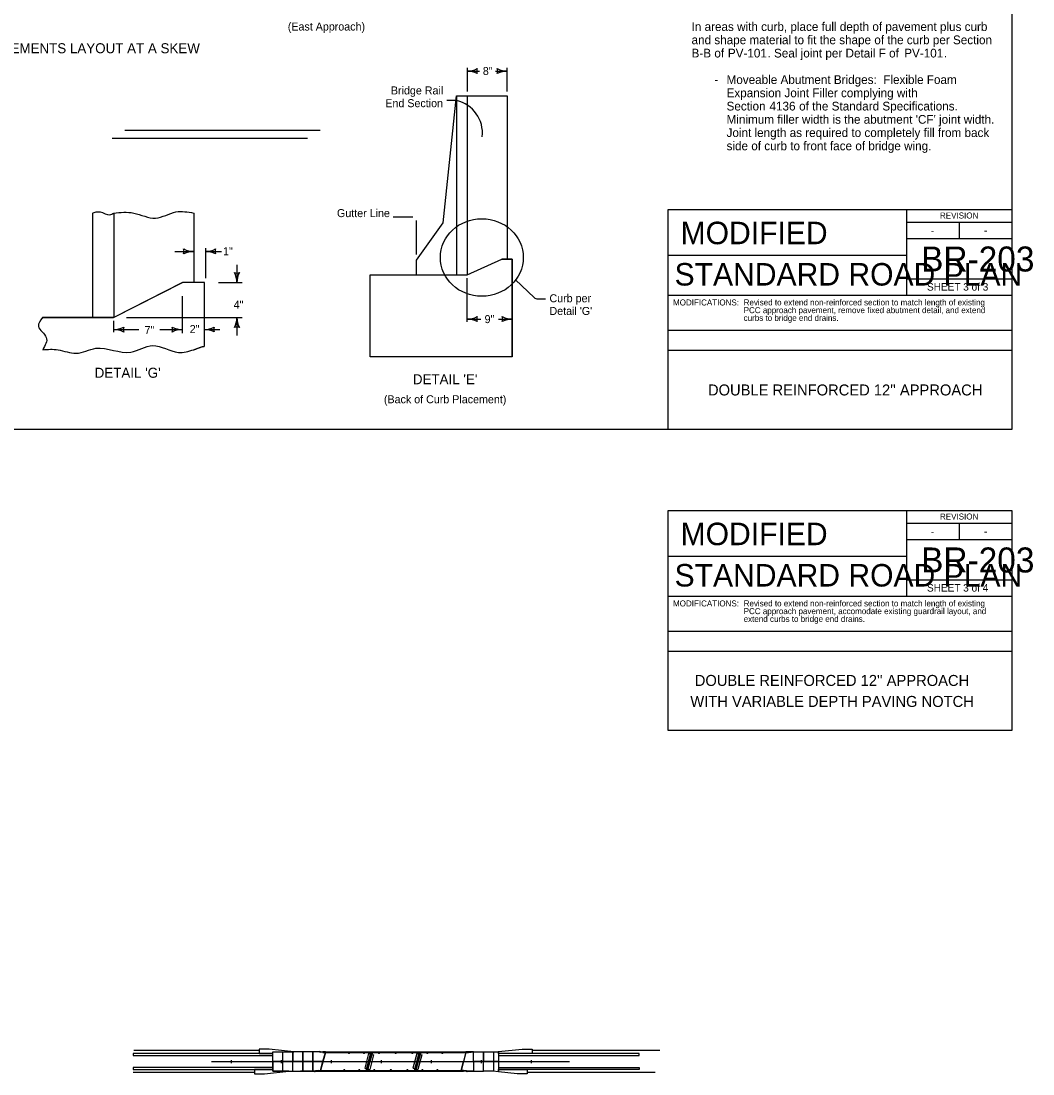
# Model space of a CAD drawing. Extents: x 5546 to 81668, y 3174 to 15999.
# Drawn here: x 18485 to 20510, y 6635 to 8741 of the extents above; entities that cross this region are included whole.
import ezdxf

# ---------------------------------------------------------------- set-up
doc = ezdxf.new("R2010")
doc.units = 0
for name, color, linetype in [('Annotation', 7, 'Continuous'), ('Level 61', 7, 'Continuous'), ('PS_BOLT', 7, 'Continuous'), ('PS_CONST', 7, 'Continuous'), ('PS_DIM', 7, 'Continuous'), ('SheetAddenda', 7, 'Continuous'), ('ShtPlotIdentification', 7, 'Continuous'), ('Table Border', 7, 'Continuous'), ('tdCoLegendColorEntry', 7, 'Continuous'), ('tdCoLegendTitle', 7, 'Continuous'), ('tdCoShieldCoRte', 7, 'Continuous'), ('tdCoShieldUsRte', 7, 'Continuous')]:
    doc.layers.add(name, color=color, linetype=linetype)

msp = doc.modelspace()

# ---------------------------------------------------------------- linework, layer by layer
at = {"layer": 'Annotation'}
for p, q in [((19082.1, 6679.9), (19082.2, 6680)), ((19082.1, 6679.9), (19083.8, 6679.9)), ((19082.1, 6679.9), (19083.8, 6678.9)), ((19082.5, 6680.6), (19082.2, 6680)), ((19082.2, 6680), (19083.9, 6679)), ((19084.1, 6679.7), (19082.5, 6680.6)), ((19083.8, 6679.9), (19089.1, 6679.9)), ((19089.1, 6678.9), (19083.8, 6678.9)), ((19089.1, 6679), (19083.9, 6679)), ((19084.4, 6679.7), (19084.4, 6678.9)), ((19094.1, 6678.3), (19084.4, 6642.3)), ((19089.1, 6678.3), (19084.6, 6678.9)), ((19085.5, 6679.7), (19085.5, 6678.9)), ((19086.2, 6679.7), (19086.2, 6678.9)), ((19089.1, 6679.9), (19380.1, 6679.9)), ((19089.1, 6678.3), (19089.1, 6679.9)), ((19094.3, 6679.7), (19089.1, 6679.7)), ((19094.3, 6679), (19089.1, 6679)), ((19094.3, 6678.9), (19089.1, 6678.9)), ((19089.1, 6678.3), (19380.1, 6678.3)), ((19094.1, 6678.3), (19094.1, 6679.9)), ((19180.3, 6676.1), (19172.6, 6647.2)), ((19185.1, 6679.8), (19174.9, 6641.6)), ((19188.2, 6679), (19177.9, 6640.8)), ((19180.3, 6676.1), (19190.5, 6673.4)), ((19185.1, 6679.8), (19188.2, 6679)), ((19276.8, 6676.1), (19269.1, 6647.2)), ((19281.6, 6679.8), (19271.4, 6641.6)), ((19284.7, 6679), (19274.5, 6640.8)), ((19276.8, 6676.1), (19287, 6673.4)), ((19281.6, 6679.8), (19284.7, 6679)), ((19375.2, 6678.3), (19365.5, 6642.3)), ((19380.1, 6679.7), (19374.9, 6679.7)), ((19380.1, 6679), (19374.9, 6679)), ((19380.1, 6678.9), (19374.9, 6678.9)), ((19375.2, 6678.3), (19375.2, 6679.9)), ((19380.1, 6678.3), (19380.1, 6679.9)), ((19385.4, 6679.9), (19380.1, 6679.9)), ((19380.1, 6679), (19385.3, 6679)), ((19380.1, 6678.9), (19385.4, 6678.9)), ((19380.1, 6678.3), (19384.6, 6678.9)), ((19383, 6679.7), (19383, 6678.9)), ((19383.7, 6679.7), (19383.7, 6678.9)), ((19384.8, 6679.7), (19384.8, 6678.9)), ((19385.2, 6679.7), (19386.7, 6680.6)), ((19387, 6680), (19385.3, 6679)), ((19387.1, 6679.9), (19385.4, 6679.9)), ((19387.1, 6679.9), (19385.4, 6678.9)), ((19386.7, 6680.6), (19387, 6680)), ((19387.1, 6679.9), (19387, 6680)), ((19182.8, 6669.8), (19177.9, 6651.4)), ((19185.2, 6669.2), (19180.3, 6650.8)), ((19190.5, 6673.4), (19182.7, 6644.5)), ((19182.8, 6671.3), (19185.9, 6670.5)), ((19279.3, 6669.8), (19274.4, 6651.4)), ((19281.7, 6669.2), (19276.8, 6650.8)), ((19287, 6673.4), (19279.2, 6644.5)), ((19279.3, 6671.3), (19282.4, 6670.5)), ((19072.5, 6640.7), (19074.2, 6641.7)), ((19072.5, 6640.6), (19074.2, 6641.5)), ((19072.5, 6640.7), (19074.1, 6640.7)), ((19072.5, 6640.7), (19072.5, 6640.6)), ((19072.9, 6640), (19072.5, 6640.6)), ((19074.4, 6640.9), (19072.9, 6640)), ((19074.1, 6640.7), (19079.5, 6640.7)), ((19079.5, 6641.7), (19074.2, 6641.7)), ((19079.5, 6641.5), (19074.2, 6641.5)), ((19074.8, 6640.9), (19074.8, 6641.7)), ((19079.5, 6642.3), (19075, 6641.7)), ((19075.9, 6640.9), (19075.9, 6641.7)), ((19076.5, 6640.9), (19076.5, 6641.7)), ((19079.5, 6642.3), (19079.5, 6640.7)), ((19079.5, 6640.9), (19079.5, 6642.3)), ((19079.5, 6642.3), (19370.5, 6642.3)), ((19084.7, 6641.7), (19079.5, 6641.7)), ((19084.7, 6641.5), (19079.5, 6641.5)), ((19084.7, 6640.9), (19079.5, 6640.9)), ((19079.5, 6640.7), (19370.5, 6640.7)), ((19084.4, 6640.7), (19084.4, 6642.3)), ((19172.6, 6647.2), (19182.7, 6644.5)), ((19174.9, 6641.6), (19177.9, 6640.8)), ((19177.2, 6650.1), (19180.2, 6649.3)), ((19269.1, 6647.2), (19279.2, 6644.5)), ((19271.4, 6641.6), (19274.5, 6640.8)), ((19273.7, 6650.1), (19276.7, 6649.3)), ((19370.5, 6641.5), (19365.2, 6641.5)), ((19370.5, 6640.9), (19365.2, 6640.9)), ((19370.5, 6641.7), (19365.3, 6641.7)), ((19365.5, 6640.7), (19365.5, 6642.3)), ((19370.5, 6642.3), (19370.5, 6640.7)), ((19370.5, 6642.3), (19374.9, 6641.7)), ((19370.5, 6641.7), (19375.7, 6641.7)), ((19370.5, 6641.5), (19375.7, 6641.5)), ((19375.8, 6640.7), (19370.5, 6640.7)), ((19373.4, 6640.9), (19373.4, 6641.7)), ((19374.1, 6640.9), (19374.1, 6641.7)), ((19375.1, 6640.9), (19375.1, 6641.7)), ((19375.5, 6640.9), (19377, 6640)), ((19376.6, 6641.2), (19375.7, 6641.7)), ((19377.4, 6640.6), (19375.7, 6641.5)), ((19377.5, 6640.7), (19375.8, 6640.7)), ((19377, 6640), (19377.4, 6640.6)), ((19377.5, 6640.7), (19377.4, 6640.6))]:
    msp.add_line(p, q, dxfattribs=at)
for points in [[(19084.1, 6679.7), (19089.1, 6679.7), (19089.1, 6679.7), (19089.1, 6679.7)], [(19385.2, 6679.7), (19380.1, 6679.7), (19380.1, 6679.7), (19380.1, 6679.7)], [(19074.4, 6640.9), (19079.5, 6640.9), (19079.5, 6640.9), (19079.5, 6640.9)], [(19375.5, 6640.9), (19370.5, 6640.9), (19370.5, 6640.9), (19370.5, 6640.9)]]:
    msp.add_lwpolyline(points, dxfattribs=at)
for centre, radius, start, end in [((19141.4, 6678.3), 1.5, 180, 0), ((19171.4, 6678.3), 1.5, 180, 0), ((19201.4, 6678.3), 1.5, 180, 0), ((19234.6, 6678.3), 1.5, 180, 0), ((19267.9, 6678.3), 1.5, 180, 0), ((19297.9, 6678.3), 1.5, 180, 0), ((19327.9, 6678.3), 1.5, 180, 0), ((19184, 6669.5), 1.25, 345, 165), ((19280.5, 6669.5), 1.25, 345, 165), ((19131.7, 6642.3), 1.5, 360, 180), ((19161.7, 6642.3), 1.5, 360, 180), ((19179.1, 6651.1), 1.25, 165, 345), ((19191.7, 6642.3), 1.5, 360, 180), ((19225, 6642.3), 1.5, 360, 180), ((19258.2, 6642.3), 1.5, 360, 180), ((19275.6, 6651.1), 1.25, 165, 345), ((19288.2, 6642.3), 1.5, 360, 180), ((19318.2, 6642.3), 1.5, 360, 180)]:
    msp.add_arc(centre, radius, start, end, dxfattribs=at)
at = {"layer": 'Level 61'}
msp.add_lwpolyline([(17332.5, 9944), (20467.5, 9944), (20467.5, 7924), (17332.5, 7924)], close=True, dxfattribs=at)
at = {"layer": 'PS_CONST'}
for centre, radius, start, end in [((19377.7, 8683.5), 42.5, 270, 298.0725), ((19377.7, 8598.5), 42.5, 61.9275, 90), ((19413.3, 8641), 16.4, 162.2666, 197.7334), ((19422.3, 8641), 16.4, 342.2666, 17.7333), ((19458, 8683.5), 42.5, 241.9275, 270), ((19458, 8598.5), 42.5, 90, 118.0725), ((18794.8, 8280.3), 16.4, 342.2666, 17.7333), ((18830.5, 8322.8), 42.5, 241.9275, 270), ((18830.5, 8237.8), 42.5, 90, 118.0725), ((18854.3, 8322.8), 42.5, 270, 298.0725), ((18854.3, 8237.8), 42.5, 61.9275, 90), ((18889.9, 8280.3), 16.4, 162.2666, 197.7334), ((18917, 8253.6), 16.4, 252.2666, 287.7333), ((18874.5, 8218), 42.5, 360, 28.0725), ((18959.5, 8218), 42.5, 151.9275, 180), ((19377.7, 8187.5), 42.5, 270, 298.0725), ((19413.3, 8145), 16.4, 162.2666, 197.7334), ((19432.3, 8145), 16.4, 342.2666, 17.7333), ((19468, 8187.5), 42.5, 241.9275, 270), ((18670.5, 8166.7), 42.5, 270, 298.0725), ((18706.1, 8124.2), 16.4, 162.2666, 197.7334), ((18771.9, 8124.2), 16.4, 342.2666, 17.7333), ((18807.6, 8166.7), 42.5, 241.9275, 270), ((18874.5, 8148.1), 42.5, 331.9275, 360), ((18917, 8112.4), 16.4, 72.2666, 107.7334), ((18959.5, 8148.1), 42.5, 180, 208.0725), ((19377.7, 8102.5), 42.5, 61.9275, 90), ((19468, 8102.5), 42.5, 90, 118.0725), ((18670.5, 8081.7), 42.5, 61.9275, 90), ((18807.6, 8081.7), 42.5, 90, 118.0725)]:
    msp.add_arc(centre, radius, start, end, dxfattribs=at)
at = {"layer": 'PS_DIM'}
for p, q in [((19377.7, 8641), (19402.4, 8641)), ((19378, 8600.4), (19378, 8647.7)), ((19434.3, 8641), (19458, 8641)), ((19458, 8600.4), (19458, 8647.7)), ((19329.7, 8337.3), (19356.4, 8591.3)), ((19356.4, 8591.3), (19457.7, 8591.3)), ((19356.4, 8591.3), (19356.4, 8233.7)), ((19377.7, 8591.3), (19377.7, 8233.7)), ((19457.7, 8591.3), (19457.7, 8265.2)), ((19356.7, 8582.1), (19337.2, 8582.1)), ((18667.5, 8506.6), (19058.4, 8506.6)), ((18692.8, 8522.6), (19083.7, 8522.6)), ((18627.8, 8357.1), (18627.8, 8148)), ((18670.5, 8357.1), (18670.5, 8148)), ((18830.5, 8357.1), (18830.5, 8218)), ((19229.9, 8349.7), (19268.8, 8349.7)), ((19276.3, 8274.3), (19276.3, 8342.2)), ((19276.3, 8262.6), (19329.7, 8337.3)), ((19457.7, 8296.9), (19457.7, 8265.2)), ((18792.8, 8280.3), (18830.5, 8280.3)), ((18854.3, 8286.8), (18854.3, 8226.8)), ((18854.3, 8280.3), (18886.5, 8280.3)), ((18830.5, 8274.4), (18830.5, 8218)), ((19276.3, 8233.7), (19276.3, 8262.6)), ((19377.7, 8233.7), (19446.8, 8265.2)), ((19468, 8265.2), (19446.8, 8265.2)), ((19446.8, 8265.2), (19468, 8265.2)), ((19468, 8069.5), (19468, 8265.2)), ((19468, 8265.2), (19468, 8069.5)), ((18917, 8253.7), (18917, 8218)), ((18852.4, 8218), (18808.2, 8218)), ((18852.4, 8090.7), (18852.4, 8218)), ((18879.9, 8218), (18927.7, 8218)), ((19377.7, 8139.8), (19377.7, 8227.1)), ((19474.6, 8223.3), (19511.7, 8188.4)), ((18807.6, 8190.6), (18807.6, 8116.7)), ((19518.6, 8185.6), (19534.4, 8185.6)), ((18552.6, 8148), (18528.3, 8148)), ((18669.3, 8148), (18528.3, 8148)), ((18528.5, 8148), (18574.5, 8147.9)), ((18574.5, 8147.9), (18552.6, 8148)), ((18670.4, 8148), (18574.5, 8147.9)), ((18574.5, 8147.9), (18670.4, 8148)), ((18670.5, 8148), (18669.3, 8148)), ((18670.4, 8141.7), (18670.4, 8118.7)), ((18696.3, 8148.1), (18927.7, 8148.1)), ((18917, 8148.1), (18917, 8112.4)), ((19377.7, 8145), (19404.8, 8145)), ((19440.6, 8145), (19468, 8145)), ((18670.5, 8124.2), (18720.6, 8124.2)), ((18762.7, 8124.2), (18807.6, 8124.2)), ((18852.5, 8124.2), (18882.9, 8124.2))]:
    msp.add_line(p, q, dxfattribs=at)
for points in [[(19377.7, 8233.7), (19446.8, 8265.2)], [(19468, 8069.5), (19183.6, 8069.5), (19183.6, 8233.7), (19329.7, 8233.6), (19377.7, 8233.7)], [(19468, 8069.5), (19183.6, 8069.5), (19183.6, 8233.7), (19329.7, 8233.6), (19377.7, 8233.7)], [(18808.2, 8218), (18670.5, 8148), (18670.4, 8148)], [(18670.4, 8148), (18808.2, 8218)], [(18852.4, 8218), (18830.5, 8218), (18808.2, 8218)], [(18852.4, 8090.7), (18852.4, 8090.7), (18852.4, 8218)]]:
    msp.add_lwpolyline(points, dxfattribs=at)
for centre, radius, start, end in [((19341.5, 8517.2), 66.7, 353.5756, 76.8823), ((19518.6, 8195.6), 10, 226.7172, 270), ((18852.5, 8164.5), 40.3, 270, 298.0725), ((18886.3, 8124.2), 15.6, 162.2666, 197.7334), ((18852.5, 8083.8), 40.3, 61.9275, 90)]:
    msp.add_arc(centre, radius, start, end, dxfattribs=at)
msp.add_ellipse((19407, 8268.2), major_axis=(83, 0), ratio=0.93542, dxfattribs=at)
for points in [[(18627.8, 8357.1), (18643.5, 8359.5), (18662.5, 8353.7), (18670.5, 8357.1)], [(18670.5, 8357.1), (18710.5, 8357.1), (18754.3, 8347), (18795.1, 8359.3), (18830.5, 8357.1)], [(18528.3, 8148), (18520, 8130.4), (18535.7, 8108.2), (18528.5, 8083.7)], [(18528.3, 8148), (18520, 8130.4), (18535.7, 8108.2), (18528.5, 8083.7)], [(18528.5, 8083.7), (18559.1, 8083.7), (18595.2, 8076.7), (18634.9, 8086.6), (18704.9, 8079), (18748.6, 8091.9), (18800, 8078.5), (18830.5, 8083.7)], [(18528.5, 8083.7), (18559.1, 8083.7), (18595.2, 8076.7), (18634.9, 8086.6), (18704.9, 8079), (18748.6, 8091.9), (18800, 8078.5), (18830.5, 8083.7)], [(18830.5, 8083.7), (18844.5, 8088.8), (18849.8, 8090.3)]]:
    msp.add_spline(points, degree=3, dxfattribs=at)
msp.add_open_spline([(18830.5, 8083.7), (18831.4, 8084), (18832.3, 8084.3), (18833.2, 8084.6), (18834.1, 8084.9), (18835, 8085.3), (18836, 8085.6), (18837.8, 8086.3), (18839.6, 8087.1), (18841.5, 8087.8), (18843.3, 8088.4), (18845.1, 8089.1), (18846.9, 8089.6), (18847.8, 8089.9), (18848.8, 8090.1), (18849.7, 8090.3), (18850.1, 8090.4), (18850.6, 8090.5), (18851.1, 8090.5), (18851.5, 8090.6), (18852, 8090.6), (18852.4, 8090.7)], degree=3, dxfattribs=at)
at = {"layer": 'ShtPlotIdentification'}
for p, q in [((18961.7, 6682.3), (18710.5, 6682.3)), ((19763.2, 6682.3), (19507.6, 6682.3)), ((18952, 6638.3), (18709.7, 6638.3)), ((19753.6, 6638.3), (19497.9, 6638.3))]:
    msp.add_line(p, q, dxfattribs=at)
at = {"layer": 'Table Border'}
for p, q in [((18989.2, 6640.7), (18989.2, 6679.9)), ((18989.2, 6679.9), (19009.2, 6679.9)), ((19009.2, 6640.7), (19009.2, 6679.9)), ((19009.2, 6679.9), (19029.2, 6679.9)), ((19029.2, 6640.7), (19029.2, 6680)), ((19053.8, 6679.9), (19053.8, 6679.4)), ((19083, 6679.4), (19053.8, 6679.4)), ((19386.2, 6679.4), (19415.4, 6679.4)), ((19415.4, 6679.9), (19415.4, 6679.4)), ((19430.3, 6679.9), (19430.3, 6640.6)), ((19073.3, 6641.2), (19044.2, 6641.2)), ((19044.2, 6640.7), (19044.2, 6641.2)), ((19376.6, 6641.2), (19405.8, 6641.2)), ((19405.8, 6640.7), (19405.8, 6641.2))]:
    msp.add_line(p, q, dxfattribs=at)
for points in [[(18989.2, 6672.3), (18989.2, 6676.3), (18709.2, 6676.3), (18709.2, 6672.3)], [(18989.2, 6676.3), (18989.2, 6679.9), (19030.6, 6679.9), (18981.7, 6685.1), (18961.7, 6685.1), (18961.7, 6676.3)], [(19029.2, 6660.3), (19049.2, 6660.3), (19049.2, 6679.9), (19029.2, 6679.9)], [(19049.2, 6660.3), (19069.2, 6660.3), (19069.2, 6679.9), (19049.2, 6679.9)], [(19069.2, 6679.9), (19069.2, 6660.3), (19089.2, 6660.3), (19094.1, 6678.3), (19089.1, 6678.3), (19084.6, 6678.9), (19083.8, 6678.9), (19082.1, 6679.9)], [(19370.3, 6660.3), (19390.3, 6660.3), (19390.3, 6679.9), (19387.1, 6679.9), (19385.4, 6678.9), (19384.6, 6678.9), (19380.1, 6678.3), (19375.2, 6678.3)], [(19390.3, 6660.3), (19390.3, 6679.9), (19410.3, 6679.9), (19410.3, 6660.3)], [(19410.3, 6660.3), (19410.3, 6679.9), (19438.6, 6679.9), (19440.3, 6680.1), (19440.3, 6660.3)], [(19440.3, 6676.3), (19440.3, 6680.1), (19487.6, 6685.1), (19507.6, 6685.1), (19507.6, 6676.3)], [(19440.3, 6676.3), (19440.3, 6672.3), (19721.7, 6672.3), (19721.7, 6676.3)], [(18989.2, 6660.3), (18989.2, 6640.7), (19020.9, 6640.7), (19049.2, 6640.7), (19049.2, 6660.3)], [(19049.2, 6660.3), (19049.2, 6640.7), (19069.2, 6640.7), (19069.2, 6660.3)], [(19069.2, 6660.3), (19069.2, 6640.7), (19072.5, 6640.7), (19074.2, 6641.7), (19075, 6641.7), (19079.5, 6642.3), (19084.4, 6642.3), (19089.2, 6660.3)], [(19370.3, 6660.3), (19390.3, 6660.3), (19390.3, 6640.7), (19377.5, 6640.7), (19375.7, 6641.7), (19374.9, 6641.7), (19370.5, 6642.3), (19365.5, 6642.3)], [(19390.3, 6640.7), (19410.3, 6640.7), (19410.3, 6660.3), (19390.3, 6660.3)], [(19410.3, 6660.3), (19440.3, 6660.3), (19440.3, 6639.5), (19429, 6640.7), (19410.3, 6640.7)], [(18989.2, 6644.3), (18952, 6644.3), (18952, 6635.5), (18972, 6635.5), (19020.9, 6640.7), (18989.2, 6640.7)], [(19440.3, 6644.3), (19497.9, 6644.3), (19497.9, 6635.5), (19477.9, 6635.5), (19440.3, 6639.5)]]:
    msp.add_lwpolyline(points, close=True, dxfattribs=at)
for points in [[(18989.2, 6648.3), (18709.2, 6648.3), (18709.2, 6644.3), (18989.2, 6644.3)], [(19440.3, 6648.3), (19721.7, 6648.3), (19721.7, 6644.3), (19440.3, 6644.3)]]:
    msp.add_lwpolyline(points, dxfattribs=at)
at = {"layer": 'tdCoLegendColorEntry'}
for p, q in [((18866, 6660.3), (19582.5, 6660.3)), ((18905.8, 6663.3), (18905.8, 6657.3)), ((19005.8, 6663.3), (19005.8, 6657.3)), ((19105.8, 6663.3), (19105.8, 6657.3)), ((19205.8, 6663.3), (19205.8, 6657.3)), ((19305.8, 6663.3), (19305.8, 6657.3)), ((19405.8, 6663.3), (19405.8, 6657.3)), ((19505.8, 6663.3), (19505.8, 6657.3))]:
    msp.add_line(p, q, dxfattribs=at)
at = {"layer": 'tdCoLegendTitle'}
for p, q in [((20256.6, 8364), (20256.6, 8272.7)), ((20256.6, 8339.1), (20467.5, 8339.1)), ((20362.1, 8339.1), (20362.1, 8305.9)), ((20256.6, 8305.9), (20467.5, 8305.9)), ((19779.5, 8272.7), (20256.6, 8272.7)), ((20256.6, 8272.7), (20256.6, 8192.7)), ((20467.5, 8224.9), (20256.6, 8224.9)), ((19779.5, 8192.7), (20467.5, 8192.7)), ((19779.5, 8122.7), (20467.5, 8122.7)), ((19779.5, 8082.7), (20467.5, 8082.7)), ((20256.6, 7762.1), (20256.6, 7670.8)), ((20256.6, 7737.2), (20467.5, 7737.2)), ((20362.1, 7737.2), (20362.1, 7704)), ((20256.6, 7704), (20467.5, 7704)), ((19779.5, 7670.8), (20256.6, 7670.8)), ((20256.6, 7670.8), (20256.6, 7590.8)), ((20467.5, 7623), (20256.6, 7623)), ((19779.5, 7590.8), (20467.5, 7590.8)), ((19779.5, 7520.8), (20467.5, 7520.8)), ((19779.5, 7480.8), (20467.5, 7480.8)), ((19779.5, 7480.8), (20467.5, 7480.8))]:
    msp.add_line(p, q, dxfattribs=at)
for points in [[(19779.5, 8364), (20467.5, 8364), (20467.5, 7924), (19779.5, 7924)], [(19779.5, 7762.1), (20467.5, 7762.1), (20467.5, 7322.1), (19779.5, 7322.1)]]:
    msp.add_lwpolyline(points, close=True, dxfattribs=at)
at = {"layer": 'tdCoShieldCoRte'}
for p, q in [((19186.8, 6679.9), (19176.3, 6640.7)), ((19283.3, 6679.9), (19272.8, 6640.7))]:
    msp.add_line(p, q, dxfattribs=at)

# ---------------------------------------------------------------- texts
at = {"layer": 'PS_BOLT'}
for s, p in [('(East Approach)', (19018.8, 8722.1)), ('(Back of Curb Placement)', (19211.1, 7976.7))]:
    msp.add_text(s, height=16, dxfattribs=at).set_placement(p)
at = {"layer": 'PS_CONST'}
msp.add_text('APPROACH PAVEMENTS LAYOUT AT A SKEW', height=20, dxfattribs=at).set_placement((18253, 8676.7))
at = {"layer": 'PS_DIM'}
for s, height, p in [('8"', 16, (19409, 8633.2)), ('Bridge Rail ', 16, (19225.1, 8594.3)), ('End Section', 16, (19213.9, 8568.8)), ('Gutter Line', 16, (19117.2, 8349)), ('1"', 16, (18889.3, 8272.8)), ('Curb per', 16, (19542.3, 8178.7)), ('4"', 16, (18910.5, 8165.9)), ("Detail 'G'", 16, (19542.3, 8153.3)), ('9"', 16, (19412.5, 8137)), ('7"', 16, (18732.2, 8115)), ('2"', 16, (18822.6, 8117.1)), ("DETAIL 'G'", 20, (18632.4, 8027.7)), ("DETAIL 'E'", 20, (19269, 8014.7))]:
    msp.add_text(s, height=height, dxfattribs=at).set_placement(p)
at = {"layer": 'SheetAddenda'}
for s, p in [('In areas with curb, place full depth of pavement plus curb', (19826.6, 8721.2)), ('and shape material to fit the shape of the curb per Section', (19826.6, 8694.7)), ('B-B of ', (19826.6, 8668.2)), ('PV-101', (19899.2, 8668.2)), ('. Seal joint per Detail F of ', (19978.5, 8668.2)), ('PV-101', (20252, 8668.2)), ('.', (20331.3, 8668.2)), ('Moveable Abutment Bridges:  Flexible Foam', (19896.6, 8615.2)), ('       -', (19826.6, 8615.2)), ('Expansion Joint Filler complying with ', (19896.6, 8588.7)), ('Section ', (19896.6, 8562.2)), ('4136', (19982.5, 8562.2)), (' of the Standard Specifications.', (20035.3, 8562.2)), ("Minimum filler width is the abutment 'CF' joint width.", (19896.6, 8535.7)), ('Joint length as required to completely fill from back ', (19896.6, 8509.2)), ('side of curb to front face of bridge wing.', (19896.6, 8482.7))]:
    msp.add_text(s, height=17.5, dxfattribs=at).set_placement(p)
at = {"layer": 'tdCoLegendTitle'}
for s, height, p in [('REVISION', 12, (20323.6, 8346.2)), ('-', 15, (20305.1, 8314.7)), ('-', 15, (20411.6, 8315.1)), ('BR-203', 50, (20285.8, 8240.2)), ('STANDARD ROAD PLAN', 45.001, (19792.6, 8212.1)), ('SHEET 3 of 3', 15, (20297.6, 8202)), ('Revised to extend non-reinforced section to match length of existing ', 12, (19930.8, 8172.4)), ('curbs to bridge end drains.', 12, (19930.8, 8141.4)), ('PCC approach pavement, remove fixed abutment detail, and extend ', 12, (19930.8, 8156.9)), ("DOUBLE REINFORCED 12'' APPROACH", 22, (19859.4, 7992.3)), ('REVISION', 12, (20323.6, 7744.2)), ('-', 15, (20305.1, 7712.7)), ('-', 15, (20411.6, 7713.2)), ('BR-203', 50, (20285.8, 7638.3)), ('STANDARD ROAD PLAN', 45.001, (19792.6, 7610.2)), ('SHEET 3 of 4', 15, (20297.6, 7600.1)), ('Revised to extend non-reinforced section to match length of existing ', 12, (19930.8, 7570.5)), ('PCC approach pavement, accomodate existing guardrail layout, and ', 12, (19930.8, 7555)), ('extend curbs to bridge end drains.', 12, (19930.8, 7539.4)), ("DOUBLE REINFORCED 12'' APPROACH", 22, (19833, 7411.4)), ('WITH VARIABLE DEPTH PAVING NOTCH', 22, (19824.1, 7369.4))]:
    msp.add_text(s, height=height, dxfattribs=at).set_placement(p)
at = {"layer": 'tdCoShieldUsRte'}
for s, height, p in [('MODIFIED', 45, (19804.6, 8294.8)), ('MODIFICATIONS:', 12, (19789.5, 8172.3)), ('MODIFIED', 45, (19804.6, 7692.9)), ('MODIFICATIONS:', 12, (19789.5, 7570.4))]:
    msp.add_text(s, height=height, dxfattribs=at).set_placement(p)

doc.saveas('drawing.dxf')
